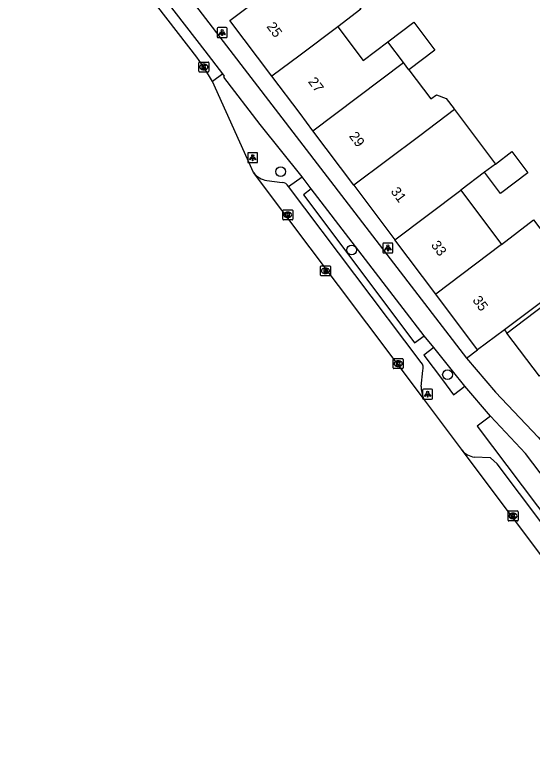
# Model space of a CAD drawing. Extents: x 161882 to 162509, y 381687 to 382379.
# Drawn here: x 161971.4 to 162023.2, y 382020.3 to 382095.4 of the extents above; entities that cross this region are included whole.
import ezdxf

# ---------------------------------------------------------------- set-up
doc = ezdxf.new("R2010")
doc.units = 0
for name, color, linetype in [('IMGEO_Berm_open', 7, 'Continuous'), ('IMGEO_Boom', 7, 'Continuous'), ('IMGEO_Fietspad_gesloten', 7, 'Continuous'), ('IMGEO_Kolk', 7, 'Continuous'), ('IMGEO_Lichtpunt', 7, 'Continuous'), ('IMGEO_Pand', 7, 'Continuous'), ('IMGEO_Pand_nummerreeks', 7, 'Continuous'), ('IMGEO_Parkeervlak_open', 7, 'Continuous'), ('IMGEO_Rijbaan_lokaal_gesloten', 7, 'Continuous'), ('IMGEO_Rioolput', 7, 'Continuous'), ('IMGEO_Voetpad_open', 7, 'Continuous')]:
    doc.layers.add(name, color=color, linetype=linetype)

msp = doc.modelspace()

# ---------------------------------------------------------------- linework, layer by layer
at = {"layer": 'IMGEO_Berm_open'}
msp.add_lwpolyline([(161992.275, 382089.501), (161991.221, 382088.734)], dxfattribs=at)
at = {"layer": 'IMGEO_Boom'}
for centre in [(161998.047, 382079.727), (162005.158, 382071.886), (162014.764, 382059.405)]:
    msp.add_circle(centre, 0.489, dxfattribs=at)
at = {"layer": 'IMGEO_Fietspad_gesloten'}
for points in [[(161959.137, 382135.841), (162016.673, 382061.059)], [(161992.275, 382089.501), (161990.474, 382091.815), (161985.541, 382098.226), (161959.864, 382131.466)], [(162000.192, 382079.199), (161996.006, 382084.434), (161992.35, 382089.181), (161992.438, 382089.281), (161992.275, 382089.501)], [(162001.1, 382078.009), (162000.192, 382079.199)], [(162012.43, 382063.283), (162010.332, 382066.01), (162001.1, 382078.009)], [(162013.382, 382062.107), (162012.43, 382063.283)], [(162016.483, 382058.236), (162015.253, 382059.771), (162013.382, 382062.107)], [(162016.673, 382061.059), (162019.582, 382057.646), (162023.854, 382053.141), (162025.74, 382050.885), (162045.217, 382025.401)], [(162019.065, 382055.253), (162016.483, 382058.236)], [(162028.557, 382043.631), (162022.572, 382051.503), (162019.065, 382055.253)]]:
    msp.add_lwpolyline(points, dxfattribs=at)
at = {"layer": 'IMGEO_Kolk'}
for p, q in [((161989.856, 382089.768), (161989.856, 382090.62)), ((161989.931, 382090.694), (161990.783, 382090.694)), ((161990.857, 382090.62), (161990.857, 382089.768)), ((161990.367, 382089.914), (161990.342, 382089.914)), ((161990.344, 382090.474), (161990.369, 382090.474)), ((161990.783, 382089.694), (161989.931, 382089.694)), ((161998.265, 382074.968), (161998.265, 382075.82)), ((161998.34, 382075.894), (161999.192, 382075.894)), ((161998.753, 382075.674), (161998.778, 382075.674)), ((161999.266, 382075.82), (161999.266, 382074.968)), ((161999.192, 382074.894), (161998.34, 382074.894)), ((161998.776, 382075.114), (161998.751, 382075.114)), ((162009.323, 382060.08), (162009.323, 382060.932)), ((162009.398, 382061.006), (162010.25, 382061.006)), ((162009.811, 382060.786), (162009.836, 382060.786)), ((162010.324, 382060.932), (162010.324, 382060.08)), ((162010.25, 382060.006), (162009.398, 382060.006)), ((162009.834, 382060.226), (162009.809, 382060.226)), ((162020.826, 382044.837), (162020.826, 382045.689)), ((162020.901, 382045.763), (162021.753, 382045.763)), ((162021.314, 382045.543), (162021.339, 382045.543)), ((162021.827, 382045.689), (162021.827, 382044.837)), ((162021.753, 382044.763), (162020.901, 382044.763)), ((162021.337, 382044.983), (162021.312, 382044.983))]:
    msp.add_line(p, q, dxfattribs=at)
for points in [[(161989.856, 382089.768), (161989.856, 382090.62)], [(161989.931, 382090.694), (161990.783, 382090.694)], [(161990.857, 382090.62), (161990.857, 382089.768)], [(161990.177, 382090.394), (161990.3, 382090.394), (161990.3, 382090.243), (161990.43, 382090.394), (161990.594, 382090.394), (161990.448, 382090.243), (161990.601, 382089.994), (161990.449, 382089.994), (161990.364, 382090.158), (161990.3, 382090.091), (161990.3, 382089.994), (161990.177, 382089.994), (161990.177, 382090.394)], [(161990.783, 382089.694), (161989.931, 382089.694)], [(161998.265, 382074.968), (161998.265, 382075.82)], [(161998.34, 382075.894), (161999.192, 382075.894)], [(161998.586, 382075.594), (161998.709, 382075.594), (161998.709, 382075.443), (161998.839, 382075.594), (161999.003, 382075.594), (161998.857, 382075.443), (161999.01, 382075.194), (161998.858, 382075.194), (161998.773, 382075.358), (161998.709, 382075.291), (161998.709, 382075.194), (161998.586, 382075.194), (161998.586, 382075.594)], [(161999.266, 382075.82), (161999.266, 382074.968)], [(161999.192, 382074.894), (161998.34, 382074.894)], [(162009.323, 382060.08), (162009.323, 382060.932)], [(162009.398, 382061.006), (162010.25, 382061.006)], [(162009.644, 382060.706), (162009.767, 382060.706), (162009.767, 382060.555), (162009.897, 382060.706), (162010.061, 382060.706), (162009.915, 382060.555), (162010.068, 382060.306), (162009.916, 382060.306), (162009.831, 382060.47), (162009.767, 382060.403), (162009.767, 382060.306), (162009.644, 382060.306), (162009.644, 382060.706)], [(162010.324, 382060.932), (162010.324, 382060.08)], [(162010.25, 382060.006), (162009.398, 382060.006)], [(162020.826, 382044.837), (162020.826, 382045.689)], [(162020.901, 382045.763), (162021.753, 382045.763)], [(162021.827, 382045.689), (162021.827, 382044.837)], [(162021.753, 382044.763), (162020.901, 382044.763)], [(162021.147, 382045.463), (162021.27, 382045.463), (162021.27, 382045.312), (162021.4, 382045.463), (162021.564, 382045.463), (162021.418, 382045.312), (162021.571, 382045.063), (162021.419, 382045.063), (162021.334, 382045.227), (162021.27, 382045.16), (162021.27, 382045.063), (162021.147, 382045.063), (162021.147, 382045.463)]]:
    msp.add_lwpolyline(points, dxfattribs=at)
for centre, start, end in [((161989.933, 382090.618), 91.55205, 178.44795), ((161989.933, 382090.618), 91.55205, 178.44795), ((161990.781, 382090.618), 1.55205, 88.44795), ((161990.781, 382090.618), 1.55205, 88.44795), ((161989.933, 382089.77), 181.55205, 268.44795), ((161989.933, 382089.77), 181.55205, 268.44795), ((161990.781, 382089.77), 271.55205, 358.44795), ((161990.781, 382089.77), 271.55205, 358.44795), ((161998.342, 382075.818), 91.55205, 178.44795), ((161998.342, 382075.818), 91.55205, 178.44795), ((161999.19, 382075.818), 1.55205, 88.44795), ((161999.19, 382075.818), 1.55205, 88.44795), ((161998.342, 382074.97), 181.55205, 268.44795), ((161998.342, 382074.97), 181.55205, 268.44795), ((161999.19, 382074.97), 271.55205, 358.44795), ((161999.19, 382074.97), 271.55205, 358.44795), ((162009.4, 382060.93), 91.55205, 178.44795), ((162009.4, 382060.93), 91.55205, 178.44795), ((162010.248, 382060.93), 1.55205, 88.44795), ((162010.248, 382060.93), 1.55205, 88.44795), ((162009.4, 382060.082), 181.55205, 268.44795), ((162009.4, 382060.082), 181.55205, 268.44795), ((162010.248, 382060.082), 271.55205, 358.44795), ((162010.248, 382060.082), 271.55205, 358.44795), ((162020.903, 382045.687), 91.55205, 178.44795), ((162020.903, 382045.687), 91.55205, 178.44795), ((162021.751, 382045.687), 1.55205, 88.44795), ((162021.751, 382045.687), 1.55205, 88.44795), ((162020.903, 382044.839), 181.55205, 268.44795), ((162020.903, 382044.839), 181.55205, 268.44795), ((162021.751, 382044.839), 271.55205, 358.44795), ((162021.751, 382044.839), 271.55205, 358.44795)]:
    msp.add_arc(centre, 0.0765, start, end, dxfattribs=at)
for centre, major_axis, ratio, start_param, end_param in [((161990.343, 382090.194), (-0.387, 0.002), 0.722429, 4.712389, 7.853982), ((161990.368, 382090.194), (-0.39, 0.002), 0.717154, 1.570796, 4.712389), ((161998.752, 382075.394), (-0.387, 0.002), 0.722429, 4.712389, 7.853982), ((161998.777, 382075.394), (-0.39, 0.002), 0.717154, 1.570796, 4.712389), ((162009.81, 382060.506), (-0.387, 0.002), 0.722429, 4.712389, 7.853982), ((162009.835, 382060.506), (-0.39, 0.002), 0.717154, 1.570796, 4.712389), ((162021.313, 382045.263), (-0.387, 0.002), 0.722429, 4.712389, 7.853982), ((162021.338, 382045.263), (-0.39, 0.002), 0.717154, 1.570796, 4.712389)]:
    msp.add_ellipse(centre, major_axis=major_axis, ratio=ratio, start_param=start_param, end_param=end_param, dxfattribs=at)
at = {"layer": 'IMGEO_Lichtpunt'}
for p, q in [((161991.697, 382094.038), (161991.697, 382093.231)), ((161991.697, 382094.038), (161991.697, 382093.231)), ((161992.599, 382094.133), (161991.791, 382094.133)), ((161992.599, 382094.133), (161991.791, 382094.133)), ((161992.693, 382093.231), (161992.693, 382094.038)), ((161992.693, 382093.231), (161992.693, 382094.038)), ((161991.791, 382093.137), (161992.599, 382093.137)), ((161991.791, 382093.137), (161992.599, 382093.137)), ((161994.752, 382081.523), (161994.752, 382080.716)), ((161994.752, 382081.523), (161994.752, 382080.716)), ((161995.654, 382081.618), (161994.846, 382081.618)), ((161995.654, 382081.618), (161994.846, 382081.618)), ((161995.748, 382080.716), (161995.748, 382081.523)), ((161995.748, 382080.716), (161995.748, 382081.523)), ((161994.846, 382080.622), (161995.654, 382080.622)), ((161994.846, 382080.622), (161995.654, 382080.622)), ((162009.198, 382072.58), (162008.39, 382072.58)), ((162009.198, 382072.58), (162008.39, 382072.58)), ((162008.296, 382072.485), (162008.296, 382071.678)), ((162008.296, 382072.485), (162008.296, 382071.678)), ((162009.292, 382071.678), (162009.292, 382072.485)), ((162009.292, 382071.678), (162009.292, 382072.485)), ((162008.39, 382071.584), (162009.198, 382071.584)), ((162008.39, 382071.584), (162009.198, 382071.584)), ((162012.275, 382057.848), (162012.275, 382057.041)), ((162012.275, 382057.848), (162012.275, 382057.041)), ((162013.177, 382057.943), (162012.369, 382057.943)), ((162013.177, 382057.943), (162012.369, 382057.943)), ((162013.271, 382057.041), (162013.271, 382057.848)), ((162013.271, 382057.041), (162013.271, 382057.848)), ((162012.369, 382056.947), (162013.177, 382056.947)), ((162012.369, 382056.947), (162013.177, 382056.947))]:
    msp.add_line(p, q, dxfattribs=at)
for points in [[(161992.071, 382093.702), (161992.11, 382093.674), (161991.922, 382093.412), (161991.884, 382093.439), (161992.071, 382093.702)], [(161992.173, 382093.654), (161992.22, 382093.654), (161992.22, 382093.332), (161992.173, 382093.332), (161992.173, 382093.654)], [(161992.283, 382093.674), (161992.321, 382093.701), (161992.508, 382093.439), (161992.469, 382093.411), (161992.283, 382093.674)], [(161995.126, 382081.187), (161995.165, 382081.159), (161994.977, 382080.897), (161994.939, 382080.924), (161995.126, 382081.187)], [(161995.228, 382081.139), (161995.275, 382081.139), (161995.275, 382080.817), (161995.228, 382080.817), (161995.228, 382081.139)], [(161995.338, 382081.159), (161995.376, 382081.186), (161995.563, 382080.924), (161995.524, 382080.896), (161995.338, 382081.159)], [(162008.67, 382072.149), (162008.709, 382072.121), (162008.521, 382071.859), (162008.483, 382071.886), (162008.67, 382072.149)], [(162008.772, 382072.101), (162008.819, 382072.101), (162008.819, 382071.779), (162008.772, 382071.779), (162008.772, 382072.101)], [(162008.882, 382072.121), (162008.92, 382072.148), (162009.107, 382071.886), (162009.068, 382071.858), (162008.882, 382072.121)], [(162012.649, 382057.512), (162012.688, 382057.484), (162012.5, 382057.222), (162012.462, 382057.249), (162012.649, 382057.512)], [(162012.861, 382057.484), (162012.899, 382057.511), (162013.086, 382057.249), (162013.047, 382057.221), (162012.861, 382057.484)], [(162012.751, 382057.464), (162012.798, 382057.464), (162012.798, 382057.142), (162012.751, 382057.142), (162012.751, 382057.464)]]:
    msp.add_lwpolyline(points, dxfattribs=at)
for centre in [(161992.196, 382093.836), (161995.251, 382081.321), (162008.795, 382072.283), (162012.774, 382057.646)]:
    msp.add_circle(centre, 0.0994, dxfattribs=at)
for centre, start, end in [((161991.791, 382094.038), 90, 180), ((161991.791, 382094.038), 90, 180), ((161992.599, 382094.038), 0, 90), ((161992.599, 382094.038), 0, 90), ((161991.791, 382093.231), 180, 270), ((161991.791, 382093.231), 180, 270), ((161992.599, 382093.231), 270, 0), ((161992.599, 382093.231), 270, 360), ((161994.846, 382081.523), 90, 180), ((161994.846, 382081.523), 90, 180), ((161995.654, 382081.523), 0, 90), ((161995.654, 382081.523), 0, 90), ((161994.846, 382080.716), 180, 270), ((161994.846, 382080.716), 180, 270), ((161995.654, 382080.716), 270, 0), ((161995.654, 382080.716), 270, 360), ((162008.39, 382072.485), 90, 180), ((162008.39, 382072.485), 90, 180), ((162009.198, 382072.485), 0, 90), ((162009.198, 382072.485), 0, 90), ((162008.39, 382071.678), 180, 270), ((162008.39, 382071.678), 180, 270), ((162009.198, 382071.678), 270, 0), ((162009.198, 382071.678), 270, 360), ((162012.369, 382057.848), 90, 180), ((162012.369, 382057.848), 90, 180), ((162013.177, 382057.848), 0, 90), ((162013.177, 382057.848), 0, 90), ((162012.369, 382057.041), 180, 270), ((162012.369, 382057.041), 180, 270), ((162013.177, 382057.041), 270, 0), ((162013.177, 382057.041), 270, 360)]:
    msp.add_arc(centre, 0.0946, start, end, dxfattribs=at)
at = {"layer": 'IMGEO_Pand'}
for points in [[(161997.181, 382089.274), (161992.969, 382094.837), (161996.819, 382097.798), (161999.5, 382099.86), (162001.814, 382101.64)], [(162001.814, 382101.64), (162001.892, 382101.537), (162003.896, 382098.887), (162005.458, 382096.822), (162005.844, 382096.311), (162006.095, 382095.979), (162003.768, 382094.228)], [(162008.793, 382092.721), (162011.391, 382094.676), (162013.495, 382091.879), (162010.898, 382089.924)], [(162003.768, 382094.228), (162000, 382091.394), (161997.181, 382089.274)], [(162003.768, 382094.228), (162006.309, 382090.852), (162008.793, 382092.721)], [(162010.357, 382090.643), (162008.793, 382092.721)], [(162001.285, 382083.821), (162010.357, 382090.643)], [(162010.898, 382089.924), (162010.357, 382090.643)], [(162010.898, 382089.924), (162013.094, 382087.006), (162013.646, 382087.422), (162014.626, 382087.049), (162015.418, 382085.997), (162015.459, 382085.942)], [(162001.285, 382083.821), (162000, 382085.529), (161997.181, 382089.274)], [(162015.459, 382085.942), (162011.976, 382083.32), (162005.39, 382078.367)], [(162015.459, 382085.942), (162019.566, 382080.487)], [(162005.39, 382078.367), (162001.285, 382083.821)], [(162019.566, 382080.487), (162021.222, 382081.733), (162022.813, 382079.62), (162020.06, 382077.548), (162018.469, 382079.661)], [(162019.566, 382080.487), (162018.469, 382079.661)], [(162018.469, 382079.661), (162016.082, 382077.865)], [(162005.39, 382078.367), (162009.496, 382072.912)], [(162009.496, 382072.912), (162016.082, 382077.865)], [(162016.082, 382077.865), (162020.16, 382072.446)], [(162020.16, 382072.446), (162023.392, 382074.893), (162027.615, 382069.316), (162024.472, 382066.904), (162020.48, 382063.901)], [(162013.6, 382067.459), (162009.496, 382072.912)], [(162020.16, 382072.446), (162013.6, 382067.459)], [(162020.714, 382063.56), (162028.32, 382069.318), (162031.58, 382065.013), (162023.974, 382059.255)], [(162017.781, 382061.904), (162013.6, 382067.459)], [(162020.48, 382063.901), (162017.781, 382061.904)], [(162023.974, 382059.255), (162020.714, 382063.56)]]:
    msp.add_lwpolyline(points, dxfattribs=at)
at = {"layer": 'IMGEO_Parkeervlak_open'}
msp.add_lwpolyline([(161996.674, 382078.842), (161998.202, 382078.626)], dxfattribs=at)
for centre, radius, start, end in [((161997.039, 382081.022), 2.21, 219.16545, 260.50671), ((161998.229, 382077.967), 0.66, 24.83559, 92.37935)]:
    msp.add_arc(centre, radius, start, end, dxfattribs=at)
at = {"layer": 'IMGEO_Rijbaan_lokaal_gesloten'}
for points in [[(161991.221, 382088.734), (161990.357, 382090.194), (161989.641, 382091.189), (161984.727, 382097.596), (161963.661, 382124.959), (161961.943, 382127.141), (161959.043, 382130.896)], [(161995.325, 382079.626), (161991.221, 382088.734)], [(162012.344, 382057.022), (161995.325, 382079.626)], [(162016.224, 382051.857), (162016.163, 382051.939), (162012.344, 382057.022)], [(162039.92, 382020.338), (162025.711, 382039.238), (162016.224, 382051.857)]]:
    msp.add_lwpolyline(points, dxfattribs=at)
at = {"layer": 'IMGEO_Rioolput'}
for p, q in [((162002.114, 382070.292), (162002.966, 382070.292)), ((162002.039, 382069.366), (162002.039, 382070.218)), ((162002.55, 382069.512), (162002.525, 382069.512)), ((162002.527, 382070.072), (162002.552, 382070.072)), ((162003.04, 382070.218), (162003.04, 382069.366)), ((162002.966, 382069.292), (162002.114, 382069.292))]:
    msp.add_line(p, q, dxfattribs=at)
for points in [[(162002.114, 382070.292), (162002.966, 382070.292)], [(162002.039, 382069.366), (162002.039, 382070.218)], [(162002.628, 382069.99), (162002.376, 382069.992), (162002.376, 382069.592)], [(162002.376, 382069.592), (162002.5, 382069.592), (162002.5, 382069.754), (162002.511, 382069.754)], [(162002.554, 382069.911), (162002.5, 382069.911), (162002.5, 382069.83)], [(162002.5, 382069.83), (162002.552, 382069.83)], [(162002.558, 382069.725), (162002.629, 382069.592), (162002.769, 382069.592), (162002.704, 382069.718)], [(162003.04, 382070.218), (162003.04, 382069.366)], [(162002.966, 382069.292), (162002.114, 382069.292)]]:
    msp.add_lwpolyline(points, dxfattribs=at)
for centre, radius, start, end in [((162002.116, 382070.216), 0.0765, 91.55205, 178.44795), ((162002.116, 382070.216), 0.0765, 91.55205, 178.44795), ((162002.964, 382070.216), 0.0765, 1.55205, 88.44795), ((162002.964, 382070.216), 0.0765, 1.55205, 88.44795), ((162002.51, 382069.701), 0.0533, 26.02933, 88.69889), ((162002.536, 382070.019), 0.19, 274.7715, 282.96867), ((162002.56, 382069.815), 0.0964, 77.00612, 93.18647), ((162002.574, 382069.872), 0.0378, 276.66336, 79.67722), ((162002.627, 382069.88), 0.109, 350.36119, 89.41601), ((162002.625, 382069.88), 0.112, 277.58423, 350.98172), ((162002.609, 382069.665), 0.108, 29.51342, 73.79051), ((162002.116, 382069.368), 0.0765, 181.55205, 268.44795), ((162002.116, 382069.368), 0.0765, 181.55205, 268.44795), ((162002.964, 382069.368), 0.0765, 271.55205, 358.44795), ((162002.964, 382069.368), 0.0765, 271.55205, 358.44795)]:
    msp.add_arc(centre, radius, start, end, dxfattribs=at)
for centre, major_axis, ratio, start_param, end_param in [((162002.526, 382069.792), (-0.387, 0.002), 0.722429, 4.712389, 7.853982), ((162002.551, 382069.792), (-0.39, 0.002), 0.717154, 1.570796, 4.712389)]:
    msp.add_ellipse(centre, major_axis=major_axis, ratio=ratio, start_param=start_param, end_param=end_param, dxfattribs=at)
at = {"layer": 'IMGEO_Voetpad_open'}
for points in [[(161998.828, 382078.244), (162000.192, 382079.199)], [(162012.114, 382060.61), (161998.828, 382078.244)], [(162001.1, 382078.009), (162000.348, 382077.394), (162009.396, 382065.347), (162011.472, 382062.582), (162012.43, 382063.283)], [(162020.48, 382063.901), (162020.714, 382063.56)], [(162013.382, 382062.107), (162012.403, 382061.371), (162014.255, 382058.895), (162015.378, 382057.395), (162016.483, 382058.236)], [(162016.673, 382061.059), (162017.781, 382061.904)], [(162012.131, 382058.23), (162012.3, 382059.825)], [(162019.065, 382055.253), (162017.721, 382054.256), (162026.753, 382042.294), (162028.557, 382043.631)], [(162039.661, 382024.01), (162019.748, 382050.471), (162019.086, 382051.072), (162017.432, 382051.154)]]:
    msp.add_lwpolyline(points, dxfattribs=at)
for centre, radius, start, end in [((162011.569, 382060.066), 0.77, 341.73581, 44.92416), ((162015.404, 382058.184), 3.273, 179.20111, 200.79861), ((162017.714, 382053.028), 1.896, 218.16833, 261.43683)]:
    msp.add_arc(centre, radius, start, end, dxfattribs=at)

# ---------------------------------------------------------------- texts
at = {"layer": 'IMGEO_Pand_nummerreeks'}
for s, rotation, p in [('25', 306.9613, (161996.599, 382094.237)), ('27', 306.96737, (162000.75, 382088.722)), ('29', 306.96703, (162004.854, 382083.269)), ('31', 306.96703, (162009.027, 382077.724)), ('33', 306.96737, (162013.065, 382072.36)), ('35', 306.96737, (162017.216, 382066.846))]:
    msp.add_text(s, height=1, rotation=rotation, dxfattribs=at).set_placement(p)

doc.saveas('drawing.dxf')
